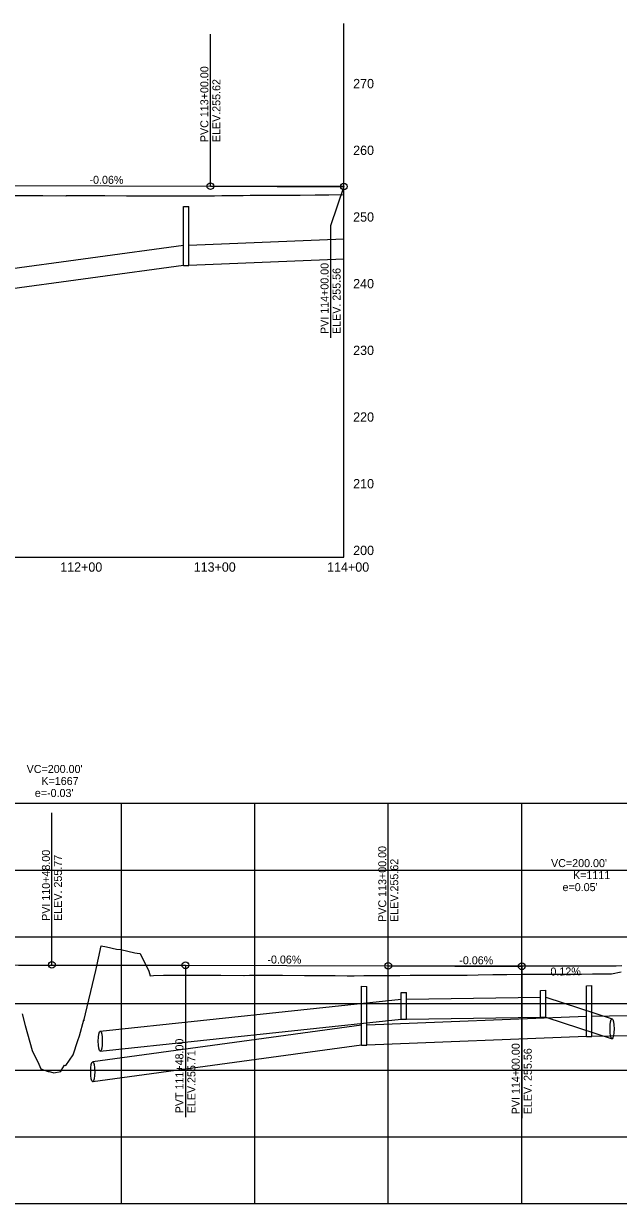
# Model space of a CAD drawing. Extents: x 1930770 to 1938778, y 596900 to 600561.
# Drawn here: x 1933419 to 1933865, y 598575 to 599459 of the extents above; entities that cross this region are included whole.
import ezdxf

# ---------------------------------------------------------------- set-up
doc = ezdxf.new("R2010")
doc.units = 0
for name, color, linetype in [('E_Tract Residual', 7, 'Continuous'), ('R_Concrete Hidden', 7, 'Continuous'), ('S_CROSS_DRAIN_ANNOT', 7, 'Continuous'), ('S_DROP_INLET_ANNOT', 7, 'Continuous'), ('S_ELECTRIC_UTILITIES_ANNOT', 7, 'Continuous'), ('S_HIST_HIGH_WATER_ANNOT', 7, 'Continuous'), ('S_SIGN_ANNOT', 7, 'Continuous'), ('S_UTILITY_POLE_ANNOT', 7, 'Continuous'), ('S_WATER_UTILITIES_ANNOT', 7, 'Continuous')]:
    doc.layers.add(name, color=color, linetype=linetype)

msp = doc.modelspace()

# ---------------------------------------------------------------- linework, layer by layer
at = {"layer": 'R_Concrete Hidden'}
for p, q in [((1933539.31, 599277.76), (1933539.31, 599322)), ((1933539.31, 599322), (1933543.31, 599321.97)), ((1933543.31, 599277.76), (1933543.31, 599321.97)), ((1933659.37, 599297.45), (1933543.31, 599292.76)), ((1933539.31, 599292.76), (1933337.92, 599265.46)), ((1933539.31, 599277.76), (1933337.92, 599250.46)), ((1933539.31, 599277.76), (1933543.31, 599277.76)), ((1933659.37, 599282.45), (1933543.31, 599277.76)), ((1933672.61, 598693.1), (1933672.61, 598737.34)), ((1933672.61, 598737.34), (1933676.61, 598737.32)), ((1933676.61, 598693.1), (1933676.61, 598737.32)), ((1933841.13, 598737.75), (1933845.13, 598737.9)), ((1933841.13, 598699.75), (1933841.13, 598737.75)), ((1933845.13, 598699.75), (1933845.13, 598737.9)), ((1933841.13, 598714.75), (1933676.61, 598708.1)), ((1933920.49, 598716.1), (1933845.13, 598714.75)), ((1933672.61, 598708.1), (1933471.22, 598680.8)), ((1933672.61, 598693.1), (1933471.22, 598665.8)), ((1933672.61, 598693.1), (1933676.61, 598693.1)), ((1933841.13, 598699.75), (1933676.61, 598693.1)), ((1933841.13, 598699.75), (1933845.13, 598699.75)), ((1933920.49, 598701.1), (1933845.13, 598699.75))]:
    msp.add_line(p, q, dxfattribs=at)
msp.add_ellipse((1933471.22, 598673.3), major_axis=(0, 7.5), ratio=0.2, dxfattribs=at)
at = {"layer": 'S_CROSS_DRAIN_ANNOT'}
for p, q in [((1933659.37, 599059.21), (1933659.37, 599459.21)), ((1932159.37, 599059.21), (1933659.37, 599059.21)), ((1932092.67, 598574.55), (1934792.67, 598574.55))]:
    msp.add_line(p, q, dxfattribs=at)
at = {"layer": 'S_ELECTRIC_UTILITIES_ANNOT'}
for p, q in [((1933559.37, 599367.33), (1933559.37, 599451.33)), ((1933559.37, 599337.33), (1933559.37, 599367.33)), ((1933609.37, 599337.18), (1933659.37, 599337.03)), ((1933659.37, 599337.03), (1933649.43, 599307.47)), ((1933659.37, 599337.03), (1933659.37, 599337.03)), ((1933649.43, 599307.47), (1933649.43, 599223.47)), ((1933440.67, 598783.42), (1933440.67, 598867.42)), ((1933692.67, 598782.67), (1933692.67, 598866.67)), ((1933440.67, 598753.42), (1933440.67, 598783.42)), ((1933692.67, 598752.67), (1933692.67, 598782.67)), ((1933390.67, 598753.27), (1933440.67, 598753.42)), ((1933440.67, 598753.42), (1933490.67, 598753.27)), ((1933540.67, 598753.12), (1933540.67, 598723.12)), ((1933742.67, 598752.52), (1933792.67, 598752.37)), ((1933792.67, 598752.37), (1933842.67, 598752.67)), ((1933792.67, 598752.37), (1933792.67, 598722.37)), ((1933540.67, 598723.12), (1933540.67, 598639.12)), ((1933792.67, 598722.37), (1933792.67, 598638.37))]:
    msp.add_line(p, q, dxfattribs=at)
for centre in [(1933559.37, 599337.33), (1933659.37, 599337.03), (1933440.67, 598753.42), (1933540.67, 598753.12), (1933692.67, 598752.67), (1933792.67, 598752.37)]:
    msp.add_circle(centre, 2.5, dxfattribs=at)
at = {"layer": 'S_HIST_HIGH_WATER_ANNOT'}
for p, q in [((1933407.37, 599337.78), (1933559.37, 599337.33)), ((1933540.67, 598753.12), (1933692.67, 598752.67))]:
    msp.add_line(p, q, dxfattribs=at)
for points in [[(1933559.37, 599337.33), (1933563.54, 599337.31), (1933567.71, 599337.3), (1933571.87, 599337.29), (1933576.04, 599337.28), (1933580.21, 599337.27), (1933584.37, 599337.27), (1933588.54, 599337.26), (1933592.71, 599337.25), (1933596.87, 599337.25), (1933601.04, 599337.24), (1933605.21, 599337.24), (1933609.37, 599337.23), (1933613.54, 599337.23), (1933617.71, 599337.23), (1933621.87, 599337.23), (1933626.04, 599337.23), (1933630.21, 599337.23), (1933634.37, 599337.23), (1933638.54, 599337.23), (1933642.71, 599337.23), (1933646.87, 599337.24), (1933651.04, 599337.24), (1933655.21, 599337.25), (1933659.37, 599337.25)], [(1933415.67, 598753.26), (1933419.83, 598753.27), (1933424, 598753.27), (1933428.17, 598753.27), (1933432.33, 598753.27), (1933436.5, 598753.27), (1933444.83, 598753.27), (1933449, 598753.27), (1933453.17, 598753.27), (1933457.33, 598753.27), (1933461.5, 598753.27), (1933465.67, 598753.26), (1933469.83, 598753.26), (1933474, 598753.26), (1933478.17, 598753.25), (1933482.33, 598753.25), (1933486.5, 598753.24), (1933490.67, 598753.24), (1933494.83, 598753.23), (1933499, 598753.22), (1933503.17, 598753.21), (1933507.33, 598753.21), (1933511.5, 598753.2), (1933515.67, 598753.19), (1933519.83, 598753.18), (1933524, 598753.17), (1933528.17, 598753.16), (1933532.33, 598753.15), (1933536.5, 598753.14), (1933540.67, 598753.12)], [(1933692.67, 598752.67), (1933696.83, 598752.65), (1933701, 598752.64), (1933705.17, 598752.63), (1933709.33, 598752.62), (1933713.5, 598752.61), (1933717.67, 598752.61), (1933721.83, 598752.6), (1933726, 598752.59), (1933730.17, 598752.59), (1933734.33, 598752.58), (1933738.5, 598752.58), (1933742.67, 598752.57), (1933746.83, 598752.57), (1933751, 598752.57), (1933755.17, 598752.57), (1933759.33, 598752.57), (1933763.5, 598752.57), (1933767.67, 598752.57), (1933771.83, 598752.57), (1933776, 598752.57), (1933780.17, 598752.58), (1933784.33, 598752.58), (1933788.5, 598752.59), (1933796.83, 598752.6), (1933801, 598752.61), (1933805.17, 598752.61), (1933809.33, 598752.62), (1933813.5, 598752.63), (1933817.67, 598752.64), (1933821.83, 598752.65), (1933826, 598752.67), (1933830.17, 598752.68), (1933834.33, 598752.69), (1933838.5, 598752.71), (1933842.67, 598752.72), (1933846.83, 598752.74), (1933851, 598752.76), (1933855.17, 598752.77), (1933859.33, 598752.79), (1933863.5, 598752.81), (1933867.67, 598752.83)]]:
    msp.add_lwpolyline(points, dxfattribs=at)
at = {"layer": 'S_SIGN_ANNOT'}
for p, q in [((1933702.36, 598712.65), (1933702.36, 598732.78)), ((1933702.36, 598732.78), (1933706.36, 598732.75)), ((1933706.36, 598712.65), (1933706.36, 598732.75)), ((1933706.36, 598727.65), (1933806.64, 598729.1)), ((1933806.64, 598734.09), (1933810.64, 598734.36)), ((1933806.64, 598714.1), (1933806.64, 598734.09)), ((1933810.64, 598714.1), (1933810.64, 598734.36)), ((1933810.64, 598729.1), (1933860.32, 598713)), ((1933476.91, 598703.7), (1933702.36, 598727.65)), ((1933476.91, 598688.7), (1933702.36, 598712.65)), ((1933702.36, 598712.65), (1933706.36, 598712.65)), ((1933706.36, 598712.65), (1933806.64, 598714.1)), ((1933806.64, 598714.1), (1933810.64, 598714.1)), ((1933810.64, 598714.1), (1933860.32, 598698))]:
    msp.add_line(p, q, dxfattribs=at)
for centre in [(1933860.32, 598705.5), (1933476.91, 598696.2)]:
    msp.add_ellipse(centre, major_axis=(0, 7.5), ratio=0.2, dxfattribs=at)
at = {"layer": 'S_UTILITY_POLE_ANNOT'}
for p, q in [((1932092.67, 598874.55), (1934792.67, 598874.55)), ((1932092.67, 598874.55), (1934792.67, 598874.55)), ((1933492.67, 598574.55), (1933492.67, 598874.55)), ((1933592.67, 598574.55), (1933592.67, 598874.55)), ((1933692.67, 598574.55), (1933692.67, 598874.55)), ((1933792.67, 598574.55), (1933792.67, 598874.55)), ((1932092.67, 598824.55), (1934792.67, 598824.55)), ((1932092.67, 598774.55), (1934792.67, 598774.55)), ((1932092.67, 598724.55), (1934792.67, 598724.55)), ((1932092.67, 598674.55), (1934792.67, 598674.55)), ((1932092.67, 598624.55), (1934792.67, 598624.55))]:
    msp.add_line(p, q, dxfattribs=at)
at = {"layer": 'S_WATER_UTILITIES_ANNOT'}
for points in [[(1933412.46, 599330.35), (1933425.19, 599330.29), (1933426.69, 599330.3), (1933428.02, 599330.31), (1933433.88, 599330.28), (1933451.16, 599330.18), (1933451.34, 599330.18), (1933451.52, 599330.19), (1933455.31, 599330.25), (1933456.33, 599330.27), (1933461.72, 599330.36), (1933461.99, 599330.34), (1933476.74, 599330.26), (1933478.98, 599330.25), (1933480.19, 599330.25), (1933496.61, 599330.15), (1933498.16, 599330.15), (1933499.24, 599330.15), (1933514.68, 599330.06), (1933519.59, 599330.03), (1933528.68, 599329.97), (1933533.83, 599329.96), (1933541.02, 599330.05), (1933549.36, 599330.15), (1933556.83, 599330.04), (1933562.44, 599330.13), (1933567.92, 599330.21), (1933575.7, 599330.33), (1933583.87, 599330.42), (1933589.16, 599330.47), (1933595.71, 599330.47), (1933596.17, 599330.47), (1933605.29, 599330.47), (1933616.66, 599330.46), (1933618.39, 599330.44), (1933626.72, 599330.59), (1933637.81, 599330.79), (1933640.04, 599330.77), (1933648.15, 599330.91), (1933658.92, 599331.1), (1933659.37, 599331.09)], [(1933418.39, 598716.82), (1933420.5, 598708.03), (1933424.14, 598695.53), (1933425.79, 598689.21), (1933430.81, 598679.02), (1933432.42, 598675.56), (1933437.09, 598673.75), (1933437.74, 598673.58), (1933438.26, 598673.45), (1933438.62, 598673.36), (1933441.31, 598672.68), (1933442, 598672.58), (1933447.35, 598673.56), (1933447.63, 598674.23), (1933450, 598678.21), (1933450.99, 598677.98), (1933456.48, 598686.05), (1933460.05, 598696.67), (1933461.23, 598700.2), (1933464.55, 598712.1), (1933464.65, 598711.48), (1933473.44, 598749.08), (1933477.55, 598767.74), (1933481.47, 598766.88), (1933488.92, 598765.25), (1933492.38, 598764.85), (1933502.9, 598762.46), (1933504.48, 598762.1), (1933506.8, 598761.83), (1933513.21, 598748.74), (1933514.19, 598745.3), (1933516.88, 598745.55), (1933524.33, 598745.61), (1933535.15, 598745.7), (1933537.68, 598745.72), (1933545.75, 598745.69), (1933558.49, 598745.63), (1933559.98, 598745.64), (1933561.32, 598745.65), (1933567.18, 598745.62), (1933584.46, 598745.52), (1933584.64, 598745.52), (1933584.82, 598745.53), (1933588.61, 598745.59), (1933589.63, 598745.61), (1933595.02, 598745.7), (1933595.28, 598745.69), (1933610.03, 598745.61), (1933612.28, 598745.59), (1933613.48, 598745.59), (1933629.91, 598745.5), (1933631.46, 598745.49), (1933632.53, 598745.49), (1933647.98, 598745.4), (1933652.88, 598745.37), (1933661.97, 598745.31), (1933667.12, 598745.3), (1933674.31, 598745.39), (1933682.65, 598745.49), (1933690.13, 598745.38), (1933695.74, 598745.47), (1933701.22, 598745.55), (1933708.99, 598745.67), (1933717.16, 598745.76), (1933722.46, 598745.81), (1933729.01, 598745.81), (1933729.46, 598745.81), (1933738.59, 598745.81), (1933749.96, 598745.8), (1933751.68, 598745.78), (1933760.02, 598745.93), (1933771.1, 598746.13), (1933773.33, 598746.11), (1933781.44, 598746.25), (1933792.22, 598746.44), (1933794.93, 598746.38), (1933802.87, 598746.42), (1933814.22, 598746.47), (1933816.14, 598746.43), (1933824.3, 598746.48), (1933836.44, 598746.55), (1933837.36, 598746.55), (1933845.72, 598746.58), (1933857.8, 598746.62), (1933859.87, 598746.61), (1933867.15, 598748.28)]]:
    msp.add_lwpolyline(points, dxfattribs=at)

# ---------------------------------------------------------------- texts
at = {"layer": 'E_Tract Residual'}
for s, rotation, p in [('-0.06%', 359.82811, (1933745.88, 598753.87)), ('0.12%', 0.34377, (1933814.19, 598745.39))]:
    msp.add_text(s, height=6, rotation=rotation, dxfattribs=at).set_placement(p)
at = {"layer": 'S_DROP_INLET_ANNOT'}
for s, p in [('270', (1933666.37, 599410.71)), ('260', (1933666.37, 599360.71)), ('250', (1933666.37, 599310.71)), ('240', (1933666.37, 599260.71)), ('230', (1933666.37, 599210.71)), ('220', (1933666.37, 599160.71)), ('210', (1933666.37, 599110.71)), ('200', (1933666.37, 599060.71)), ('112+00', (1933446.88, 599048.21)), ('113+00', (1933546.88, 599048.21)), ('114+00', (1933646.88, 599048.21))]:
    msp.add_text(s, height=7, dxfattribs=at).set_placement(p)
at = {"layer": 'S_ELECTRIC_UTILITIES_ANNOT'}
for s, rotation, p in [('PVC 113+00.00', 90, (1933557.87, 599370.33)), ('ELEV.255.62', 90, (1933566.87, 599370.33)), ('-0.06%', 359.82811, (1933468.8, 599339.1)), ('PVI 114+00.00', 90, (1933647.93, 599226.47)), ('ELEV. 255.56', 90, (1933656.93, 599226.47)), ('PVI 110+48.00', 90, (1933439.17, 598786.42)), ('ELEV. 255.77', 90, (1933448.17, 598786.42)), ('PVC 113+00.00', 90, (1933691.17, 598785.67)), ('ELEV.255.62', 90, (1933700.17, 598785.67)), ('-0.06%', 359.82811, (1933602.1, 598754.44)), ('PVT 111+48.00', 90, (1933539.17, 598642.12)), ('PVI 114+00.00', 90, (1933791.17, 598641.37)), ('ELEV.255.71', 90, (1933548.17, 598642.12)), ('ELEV. 255.56', 90, (1933800.17, 598641.37))]:
    msp.add_text(s, height=6, rotation=rotation, dxfattribs=at).set_placement(p)
for s, p in [("VC=200.00'", (1933421.71, 598897.3)), ('K=1667', (1933432.76, 598888.3)), ("e=-0.03'", (1933427.85, 598879.3)), ("VC=200.00'", (1933814.64, 598826.72)), ('K=1111', (1933831.08, 598817.72)), ("e=0.05'", (1933823.24, 598808.72))]:
    msp.add_text(s, height=6, dxfattribs=at).set_placement(p)

doc.saveas('drawing.dxf')
